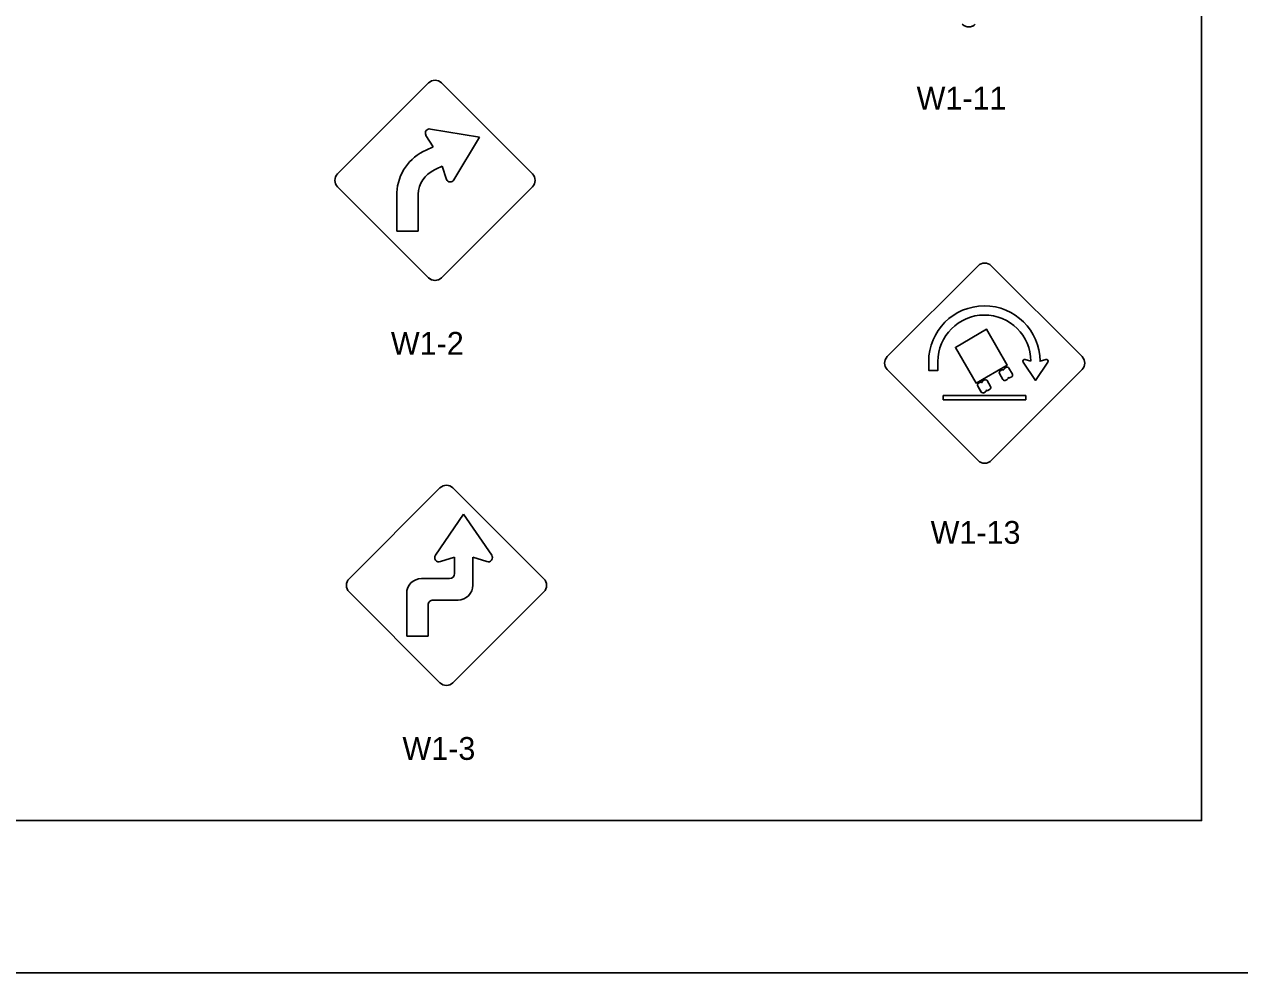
# Model space of a CAD drawing. Extents: x 42133 to 45533, y 41351 to 47951.
# Drawn here: x 43421.4 to 43820.8, y 41351.4 to 41662.9 of the extents above; entities that cross this region are included whole.
import ezdxf

# ---------------------------------------------------------------- set-up
doc = ezdxf.new("R2010")
doc.units = 0
for name, color, linetype in [('#plot_shape', 7, 'Continuous'), ('P_ODOT_PLAN_Border', 7, 'Continuous'), ('P_TRAF_SIGN_SignDetails', 7, 'Continuous')]:
    doc.layers.add(name, color=color, linetype=linetype)

msp = doc.modelspace()

# ---------------------------------------------------------------- linework, layer by layer
at = {"layer": '#plot_shape'}
msp.add_lwpolyline([(42133.34, 41351.35), (43833.34, 41351.35), (43833.34, 42451.35), (42133.34, 42451.35)], close=True, dxfattribs=at)
at = {"layer": 'P_ODOT_PLAN_Border'}
msp.add_lwpolyline([(42208.34, 41401.35), (43808.34, 41401.35), (43808.34, 42401.35), (42208.34, 42401.35)], close=True, dxfattribs=at)
at = {"layer": 'P_TRAF_SIGN_SignDetails'}
for p, q in [((43554.25, 41643.68), (43524.37, 41613.81)), ((43588.39, 41613.81), (43558.51, 41643.68)), ((43570.95, 41625.84), (43554.85, 41628.51)), ((43553.4, 41626.44), (43553.32, 41626.58)), ((43553.4, 41626.44), (43555.81, 41622.69)), ((43562.59, 41611.82), (43570.95, 41625.83)), ((43570.95, 41625.83), (43570.95, 41625.84)), ((43555.81, 41622.69), (43553.48, 41621.61)), ((43556.21, 41615.11), (43556.83, 41615.42)), ((43556.83, 41615.42), (43558.74, 41616.3)), ((43558.74, 41616.3), (43560.1, 41611.95)), ((43560.1, 41611.95), (43560.04, 41612.13)), ((43524.37, 41609.55), (43554.25, 41579.67)), ((43543.81, 41607.65), (43543.81, 41594.98)), ((43558.51, 41579.67), (43588.39, 41609.55)), ((43550.84, 41594.98), (43550.84, 41607.1)), ((43543.81, 41594.98), (43550.84, 41594.98)), ((43705.01, 41553.75), (43734.89, 41583.63)), ((43705.01, 41553.75), (43734.89, 41583.63)), ((43739.15, 41583.63), (43769.02, 41553.75)), ((43739.15, 41583.63), (43769.02, 41553.75)), ((43739.15, 41583.63), (43769.02, 41553.75)), ((43739.15, 41583.63), (43769.02, 41553.75)), ((43718.64, 41552.13), (43718.64, 41549.23)), ((43718.64, 41552.13), (43718.64, 41549.23)), ((43734.89, 41519.62), (43705.01, 41549.49)), ((43734.89, 41519.62), (43705.01, 41549.49)), ((43769.02, 41549.49), (43739.15, 41519.62)), ((43769.02, 41549.49), (43739.15, 41519.62)), ((43750.5, 41540.97), (43723.36, 41540.97)), ((43723.36, 41540.97), (43723.36, 41539.53)), ((43750.5, 41540.97), (43723.36, 41540.97)), ((43723.36, 41540.97), (43723.36, 41539.53)), ((43750.5, 41540.97), (43723.36, 41540.97)), ((43723.36, 41540.97), (43723.36, 41539.53)), ((43723.36, 41539.53), (43750.5, 41539.53)), ((43723.36, 41539.53), (43750.5, 41539.53)), ((43723.36, 41539.53), (43750.5, 41539.53)), ((43750.5, 41539.53), (43750.5, 41540.97)), ((43750.5, 41539.53), (43750.5, 41540.97)), ((43750.5, 41539.53), (43750.5, 41540.97)), ((43558, 41510.61), (43528.13, 41480.72)), ((43592.14, 41480.72), (43562.26, 41510.61)), ((43556.56, 41488.54), (43565.78, 41501.98)), ((43565.78, 41501.98), (43574.99, 41488.54)), ((43562.77, 41487.86), (43558.16, 41486.39)), ((43562.77, 41482.49), (43562.77, 41487.86)), ((43573.4, 41486.39), (43568.79, 41487.86)), ((43568.79, 41487.86), (43568.79, 41478.65)), ((43551.89, 41480.81), (43561.1, 41480.81)), ((43561.11, 41480.82), (43561.11, 41480.82)), ((43561.15, 41480.83), (43561.15, 41480.82)), ((43562.76, 41482.49), (43562.76, 41482.49)), ((43528.13, 41476.47), (43558, 41446.59)), ((43547.07, 41461.88), (43547.07, 41475.99)), ((43562.26, 41446.59), (43592.14, 41476.47)), ((43554.1, 41472.13), (43554.1, 41461.88)), ((43563.92, 41473.79), (43555.77, 41473.79)), ((43554.1, 41461.88), (43547.07, 41461.88))]:
    msp.add_line(p, q, dxfattribs=at)
for points in [[(43727.4, 41556.8), (43734.18, 41545.07), (43744.43, 41550.99), (43737.65, 41562.72)], [(43734.18, 41545.07), (43744.43, 41550.99), (43737.65, 41562.72), (43727.4, 41556.8)], [(43734.18, 41545.07), (43744.43, 41550.99), (43737.65, 41562.72), (43727.4, 41556.8)]]:
    msp.add_lwpolyline(points, close=True, dxfattribs=at)
for points in [[(43718.64, 41552.13), (43718.64, 41549.23), (43721.64, 41549.23), (43721.64, 41552.13)], [(43718.64, 41552.13), (43718.64, 41549.23), (43721.64, 41549.23), (43721.64, 41552.13)], [(43718.64, 41552.13), (43718.64, 41549.23), (43721.64, 41549.23), (43721.64, 41552.13)], [(43749.62, 41551.9), (43753.73, 41545.94), (43757.83, 41551.9)], [(43749.62, 41551.9), (43753.73, 41545.94), (43757.83, 41551.9)], [(43749.62, 41551.9), (43753.73, 41545.94), (43757.83, 41551.9)], [(43752.23, 41552.26), (43750.32, 41552.85)], [(43752.23, 41552.26), (43750.32, 41552.85)], [(43752.23, 41552.26), (43750.32, 41552.85)], [(43757.13, 41552.85), (43755.23, 41552.26), (43755.23, 41552.26)], [(43757.13, 41552.85), (43755.23, 41552.26), (43755.23, 41552.26)], [(43757.13, 41552.85), (43755.23, 41552.26), (43755.23, 41552.26)], [(43741.9, 41548.2), (43743.03, 41546.25)], [(43741.9, 41548.2), (43743.03, 41546.25)], [(43741.9, 41548.2), (43743.03, 41546.25)], [(43742.63, 41549.39), (43742.13, 41549.1)], [(43742.63, 41549.39), (43742.13, 41549.1)], [(43742.63, 41549.39), (43742.13, 41549.1)], [(43743.29, 41549.4), (43743.28, 41549.4), (43743.27, 41549.39)], [(43743.29, 41549.4), (43743.28, 41549.4), (43743.27, 41549.39)], [(43743.29, 41549.4), (43743.28, 41549.4), (43743.27, 41549.39)], [(43744.11, 41550.24), (43743.61, 41549.96)], [(43744.11, 41550.24), (43743.61, 41549.96)], [(43744.11, 41550.24), (43743.61, 41549.96)], [(43746.13, 41548.04), (43745, 41549.99)], [(43746.13, 41548.04), (43745, 41549.99)], [(43746.13, 41548.04), (43745, 41549.99)], [(43734.74, 41544.1), (43735.87, 41542.15)], [(43734.74, 41544.1), (43735.87, 41542.15)], [(43734.76, 41544.07), (43735.88, 41542.13)], [(43735.48, 41545.26), (43734.98, 41544.98)], [(43735.48, 41545.26), (43734.98, 41544.98)], [(43735.48, 41545.26), (43734.98, 41544.98)], [(43736.14, 41545.28), (43736.13, 41545.27), (43736.12, 41545.26)], [(43736.14, 41545.28), (43736.13, 41545.27), (43736.12, 41545.26)], [(43736.14, 41545.28), (43736.13, 41545.27), (43736.12, 41545.26)], [(43736.96, 41546.12), (43736.46, 41545.83)], [(43736.96, 41546.12), (43736.46, 41545.83)], [(43736.96, 41546.12), (43736.46, 41545.83)], [(43738.98, 41543.91), (43737.86, 41545.86)], [(43738.98, 41543.91), (43737.86, 41545.86)], [(43738.98, 41543.91), (43737.86, 41545.86)], [(43743.93, 41546), (43744.42, 41546.28)], [(43743.93, 41546), (43744.42, 41546.28)], [(43743.93, 41546), (43744.42, 41546.28)], [(43744.74, 41546.84), (43744.75, 41546.84), (43744.76, 41546.85)], [(43744.74, 41546.84), (43744.75, 41546.84), (43744.76, 41546.85)], [(43744.74, 41546.84), (43744.75, 41546.84), (43744.76, 41546.85)], [(43745.41, 41546.85), (43745.9, 41547.14)], [(43745.41, 41546.85), (43745.9, 41547.14)], [(43745.41, 41546.85), (43745.9, 41547.14)], [(43736.78, 41541.87), (43737.27, 41542.16)], [(43736.78, 41541.87), (43737.27, 41542.16)], [(43736.78, 41541.87), (43737.27, 41542.16)], [(43737.59, 41542.71), (43737.6, 41542.72), (43737.61, 41542.72)], [(43737.59, 41542.71), (43737.6, 41542.72), (43737.61, 41542.72)], [(43737.59, 41542.71), (43737.6, 41542.72), (43737.61, 41542.72)], [(43738.26, 41542.72), (43738.75, 41543.01)], [(43738.26, 41542.72), (43738.75, 41543.01)], [(43738.26, 41542.72), (43738.75, 41543.01)]]:
    msp.add_lwpolyline(points, dxfattribs=at)
for centre, radius, start, end in [((43731.8, 41665.06), 3.01, 225, 315), ((43731.8, 41665.06), 3.01, 225, 315), ((43731.8, 41665.06), 3.01, 243.4885, 315), ((43731.8, 41665.06), 3.01, 243.4885, 315), ((43556.38, 41641.55), 3.01, 45, 135), ((43554.55, 41627.18), 1.37, 77.1484, 205.7891), ((43559.88, 41606.85), 16.09, 113.459, 177.1639), ((43526.5, 41611.67), 3.01, 135, 225), ((43559.88, 41606.85), 9.04, 114.0343, 178.4368), ((43561.38, 41612.54), 1.41, 204.8462, 329.3412), ((43586.26, 41611.67), 3.01, 315, 45), ((43737.02, 41581.49), 3.01, 45, 135), ((43737.02, 41581.49), 3.01, 45, 135), ((43556.38, 41581.8), 3.01, 225, 296.5115), ((43556.38, 41581.8), 3.01, 225, 315), ((43707.14, 41551.62), 3.01, 135, 225), ((43707.14, 41551.62), 3.01, 135, 225), ((43766.89, 41551.62), 3.01, 315, 45), ((43766.89, 41551.62), 3.01, 315, 45), ((43737.02, 41521.74), 3.01, 225, 315), ((43737.02, 41521.74), 3.01, 225, 315), ((43737.02, 41521.74), 3.01, 243.4885, 315), ((43737.02, 41521.74), 3.01, 243.4885, 315), ((43560.13, 41508.48), 3.01, 45.0158, 135), ((43557.69, 41487.71), 1.4, 143.7001, 289.5693), ((43573.84, 41487.73), 1.41, 251.7821, 34.9485), ((43530.25, 41478.6), 3.01, 135, 225.0153), ((43551.89, 41475.99), 4.83, 90, 180), ((43561.1, 41482.49), 1.67, 270, 0), ((43590.01, 41478.6), 3.01, 315, 44.9835), ((43563.93, 41478.65), 4.86, 269.9985, 0.0015), ((43555.76, 41472.12), 1.67, 89.7132, 180.2868), ((43560.13, 41448.72), 3.01, 224.9921, 315)]:
    msp.add_arc(centre, radius, start, end, dxfattribs=at)
for centre, major_axis, start_param, end_param in [((43736.93, 41552.13), (18.3, 0), 0.006861, 3.141593), ((43736.93, 41552.13), (18.3, 0), 0.006861, 3.141593), ((43736.93, 41552.13), (18.3, 0), 0.006861, 3.141593), ((43736.93, 41552.13), (15.3, 0), 0.008204, 3.141593), ((43736.93, 41552.13), (15.3, 0), 0.008204, 3.141593), ((43736.93, 41552.13), (15.3, 0), 0.008204, 3.141593), ((43750.14, 41552.26), (0.624, 0), 1.267775, 3.744015), ((43750.14, 41552.26), (0.624, 0), 1.267775, 3.744015), ((43750.14, 41552.26), (0.624, 0), 1.267775, 3.744015), ((43757.32, 41552.26), (0.624, 0), 5.680763, 8.157003), ((43757.32, 41552.26), (0.624, 0), 5.680763, 8.157003), ((43757.32, 41552.26), (0.624, 0), 5.680763, 8.157003), ((43742.46, 41548.52), (0.646, 0), 2.834437, 3.665191), ((43742.46, 41548.52), (0.646, 0), 2.834437, 3.665191), ((43742.46, 41548.52), (0.646, 0), 2.834437, 3.665191), ((43742.63, 41548.47), (0.824, 0), 2.481084, 2.834437), ((43742.63, 41548.47), (0.824, 0), 2.481084, 2.834437), ((43742.63, 41548.47), (0.824, 0), 2.481084, 2.834437), ((43742.39, 41548.66), (0.517, 0), 2.094395, 2.481084), ((43742.39, 41548.66), (0.517, 0), 2.094395, 2.481084), ((43742.39, 41548.66), (0.517, 0), 2.094395, 2.481084), ((43742.88, 41548.94), (0.517, 0), 1.612382, 2.094395), ((43742.88, 41548.94), (0.517, 0), 1.612382, 2.094395), ((43742.88, 41548.94), (0.517, 0), 1.612382, 2.094395), ((43742.93, 41548.78), (0.68, 0), 1.108105, 1.6768), ((43742.93, 41548.78), (0.68, 0), 1.108105, 1.6768), ((43742.93, 41548.78), (0.68, 0), 1.108105, 1.6768), ((43743.25, 41549.42), (0.0323, 0), 4.249698, 5.235988), ((43743.25, 41549.42), (0.0323, 0), 4.249698, 5.235988), ((43743.25, 41549.42), (0.0323, 0), 4.249698, 5.235988), ((43743.27, 41549.43), (0.0323, 0), 5.235988, 6.222278), ((43743.27, 41549.43), (0.0323, 0), 5.235988, 6.222278), ((43743.27, 41549.43), (0.0323, 0), 5.235988, 6.222278), ((43743.98, 41549.39), (0.68, 0), 2.51199, 3.080685), ((43743.98, 41549.39), (0.68, 0), 2.51199, 3.080685), ((43743.98, 41549.39), (0.68, 0), 2.51199, 3.080685), ((43743.87, 41549.51), (0.517, 0), 2.094395, 2.576408), ((43743.87, 41549.51), (0.517, 0), 2.094395, 2.576408), ((43743.87, 41549.51), (0.517, 0), 2.094395, 2.576408), ((43744.36, 41549.8), (0.517, 0), 1.707706, 2.094395), ((43744.36, 41549.8), (0.517, 0), 1.707706, 2.094395), ((43744.36, 41549.8), (0.517, 0), 1.707706, 2.094395), ((43744.41, 41549.49), (0.824, 0), 1.354354, 1.707706), ((43744.41, 41549.49), (0.824, 0), 1.354354, 1.707706), ((43744.41, 41549.49), (0.824, 0), 1.354354, 1.707706), ((43744.44, 41549.67), (0.646, 0), 0.523599, 1.354354), ((43744.44, 41549.67), (0.646, 0), 0.523599, 1.354354), ((43744.44, 41549.67), (0.646, 0), 0.523599, 1.354354), ((43745.4, 41547.77), (0.824, 0), 5.622677, 5.976029), ((43745.4, 41547.77), (0.824, 0), 5.622677, 5.976029), ((43745.4, 41547.77), (0.824, 0), 5.622677, 5.976029), ((43745.57, 41547.72), (0.646, 0), 5.976029, 6.806784), ((43745.57, 41547.72), (0.646, 0), 5.976029, 6.806784), ((43745.57, 41547.72), (0.646, 0), 5.976029, 6.806784), ((43735.32, 41544.4), (0.646, 0), 2.834437, 3.665191), ((43735.32, 41544.4), (0.646, 0), 2.834437, 3.620466), ((43735.32, 41544.4), (0.646, 0), 2.834437, 3.620466), ((43735.48, 41544.34), (0.824, 0), 2.481084, 2.834437), ((43735.48, 41544.34), (0.824, 0), 2.481084, 2.834437), ((43735.48, 41544.34), (0.824, 0), 2.481084, 2.834437), ((43735.24, 41544.53), (0.517, 0), 2.094395, 2.481084), ((43735.24, 41544.53), (0.517, 0), 2.094395, 2.481084), ((43735.24, 41544.53), (0.517, 0), 2.094395, 2.481084), ((43735.74, 41544.81), (0.517, 0), 1.612382, 2.094395), ((43735.74, 41544.81), (0.517, 0), 1.612382, 2.094395), ((43735.74, 41544.81), (0.517, 0), 1.612382, 2.094395), ((43735.79, 41544.65), (0.68, 0), 1.108105, 1.6768), ((43735.79, 41544.65), (0.68, 0), 1.108105, 1.6768), ((43735.79, 41544.65), (0.68, 0), 1.108105, 1.6768), ((43736.1, 41545.29), (0.0323, 0), 4.249698, 5.235988), ((43736.1, 41545.29), (0.0323, 0), 4.249698, 5.235988), ((43736.1, 41545.29), (0.0323, 0), 4.249698, 5.235988), ((43736.12, 41545.3), (0.0323, 0), 5.235988, 6.222278), ((43736.12, 41545.3), (0.0323, 0), 5.235988, 6.222278), ((43736.12, 41545.3), (0.0323, 0), 5.235988, 6.222278), ((43736.84, 41545.26), (0.68, 0), 2.51199, 3.080685), ((43736.84, 41545.26), (0.68, 0), 2.51199, 3.080685), ((43736.84, 41545.26), (0.68, 0), 2.51199, 3.080685), ((43736.72, 41545.38), (0.517, 0), 2.094395, 2.576408), ((43736.72, 41545.38), (0.517, 0), 2.094395, 2.576408), ((43736.72, 41545.38), (0.517, 0), 2.094395, 2.576408), ((43737.22, 41545.67), (0.517, 0), 1.707706, 2.094395), ((43737.22, 41545.67), (0.517, 0), 1.707706, 2.094395), ((43737.22, 41545.67), (0.517, 0), 1.707706, 2.094395), ((43737.26, 41545.36), (0.824, 0), 1.354354, 1.707706), ((43737.26, 41545.36), (0.824, 0), 1.354354, 1.707706), ((43737.26, 41545.36), (0.824, 0), 1.354354, 1.707706), ((43737.3, 41545.54), (0.646, 0), 0.523599, 1.354354), ((43737.3, 41545.54), (0.646, 0), 0.523599, 1.354354), ((43737.3, 41545.54), (0.646, 0), 0.523599, 1.354354), ((43738.25, 41543.64), (0.824, 0), 5.622677, 5.976029), ((43738.25, 41543.64), (0.824, 0), 5.622677, 5.976029), ((43738.25, 41543.64), (0.824, 0), 5.622677, 5.976029), ((43738.42, 41543.59), (0.646, 0), 5.976029, 6.806784), ((43738.42, 41543.59), (0.646, 0), 5.976029, 6.806784), ((43738.42, 41543.59), (0.646, 0), 5.976029, 6.806784), ((43743.59, 41546.57), (0.646, 0), 3.665191, 4.495946), ((43743.59, 41546.57), (0.646, 0), 3.665191, 4.495946), ((43743.59, 41546.57), (0.646, 0), 3.665191, 4.495946), ((43743.63, 41546.75), (0.824, 0), 4.495946, 4.849299), ((43743.63, 41546.75), (0.824, 0), 4.495946, 4.849299), ((43743.63, 41546.75), (0.824, 0), 4.495946, 4.849299), ((43743.67, 41546.44), (0.517, 0), 4.849299, 5.235988), ((43743.67, 41546.44), (0.517, 0), 4.849299, 5.235988), ((43743.67, 41546.44), (0.517, 0), 4.849299, 5.235988), ((43744.16, 41546.73), (0.517, 0), 5.235988, 5.718), ((43744.16, 41546.73), (0.517, 0), 5.235988, 5.718), ((43744.16, 41546.73), (0.517, 0), 5.235988, 5.718), ((43744.05, 41546.85), (0.68, 0), 5.653582, 6.222278), ((43744.05, 41546.85), (0.68, 0), 5.653582, 6.222278), ((43744.05, 41546.85), (0.68, 0), 5.653582, 6.222278), ((43744.76, 41546.81), (0.0323, 0), 2.094395, 3.080685), ((43744.76, 41546.81), (0.0323, 0), 2.094395, 3.080685), ((43744.76, 41546.81), (0.0323, 0), 2.094395, 3.080685), ((43744.78, 41546.82), (0.0323, 0), 1.108105, 2.094395), ((43744.78, 41546.82), (0.0323, 0), 1.108105, 2.094395), ((43744.78, 41546.82), (0.0323, 0), 1.108105, 2.094395), ((43745.1, 41547.46), (0.68, 0), 4.249698, 4.818393), ((43745.1, 41547.46), (0.68, 0), 4.249698, 4.818393), ((43745.1, 41547.46), (0.68, 0), 4.249698, 4.818393), ((43745.15, 41547.3), (0.517, 0), 4.753975, 5.235988), ((43745.15, 41547.3), (0.517, 0), 4.753975, 5.235988), ((43745.15, 41547.3), (0.517, 0), 4.753975, 5.235988), ((43745.64, 41547.58), (0.517, 0), 5.235988, 5.622677), ((43745.64, 41547.58), (0.517, 0), 5.235988, 5.622677), ((43745.64, 41547.58), (0.517, 0), 5.235988, 5.622677), ((43736.44, 41542.45), (0.646, 0), 3.620466, 4.495946), ((43736.44, 41542.45), (0.646, 0), 3.620466, 4.495946), ((43736.44, 41542.45), (0.646, 0), 3.665191, 4.495946), ((43736.48, 41542.62), (0.824, 0), 4.495946, 4.849299), ((43736.48, 41542.62), (0.824, 0), 4.495946, 4.849299), ((43736.48, 41542.62), (0.824, 0), 4.495946, 4.849299), ((43736.52, 41542.32), (0.517, 0), 4.849299, 5.235988), ((43736.52, 41542.32), (0.517, 0), 4.849299, 5.235988), ((43736.52, 41542.32), (0.517, 0), 4.849299, 5.235988), ((43737.01, 41542.6), (0.517, 0), 5.235988, 5.718), ((43737.01, 41542.6), (0.517, 0), 5.235988, 5.718), ((43737.01, 41542.6), (0.517, 0), 5.235988, 5.718), ((43736.9, 41542.73), (0.68, 0), 5.653582, 6.222278), ((43736.9, 41542.73), (0.68, 0), 5.653582, 6.222278), ((43736.9, 41542.73), (0.68, 0), 5.653582, 6.222278), ((43737.61, 41542.68), (0.0323, 0), 2.094395, 3.080685), ((43737.61, 41542.68), (0.0323, 0), 2.094395, 3.080685), ((43737.61, 41542.68), (0.0323, 0), 2.094395, 3.080685), ((43737.63, 41542.69), (0.0323, 0), 1.108105, 2.094395), ((43737.63, 41542.69), (0.0323, 0), 1.108105, 2.094395), ((43737.63, 41542.69), (0.0323, 0), 1.108105, 2.094395), ((43737.95, 41543.33), (0.68, 0), 4.249698, 4.818393), ((43737.95, 41543.33), (0.68, 0), 4.249698, 4.818393), ((43737.95, 41543.33), (0.68, 0), 4.249698, 4.818393), ((43738, 41543.17), (0.517, 0), 4.753975, 5.235988), ((43738, 41543.17), (0.517, 0), 4.753975, 5.235988), ((43738, 41543.17), (0.517, 0), 4.753975, 5.235988), ((43738.49, 41543.46), (0.517, 0), 5.235988, 5.622677), ((43738.49, 41543.46), (0.517, 0), 5.235988, 5.622677), ((43738.49, 41543.46), (0.517, 0), 5.235988, 5.622677)]:
    msp.add_ellipse(centre, major_axis=major_axis, ratio=0.999869, start_param=start_param, end_param=end_param, dxfattribs=at)

# ---------------------------------------------------------------- texts
for s, p in [('W1-11', (43714.65, 41634.91)), ('W1-2', (43541.86, 41554.36)), ('W1-13', (43719.26, 41492.25)), ('W1-3', (43545.66, 41421.27))]:
    msp.add_text(s, height=7.5, dxfattribs=at).set_placement(p)

doc.saveas('drawing.dxf')
